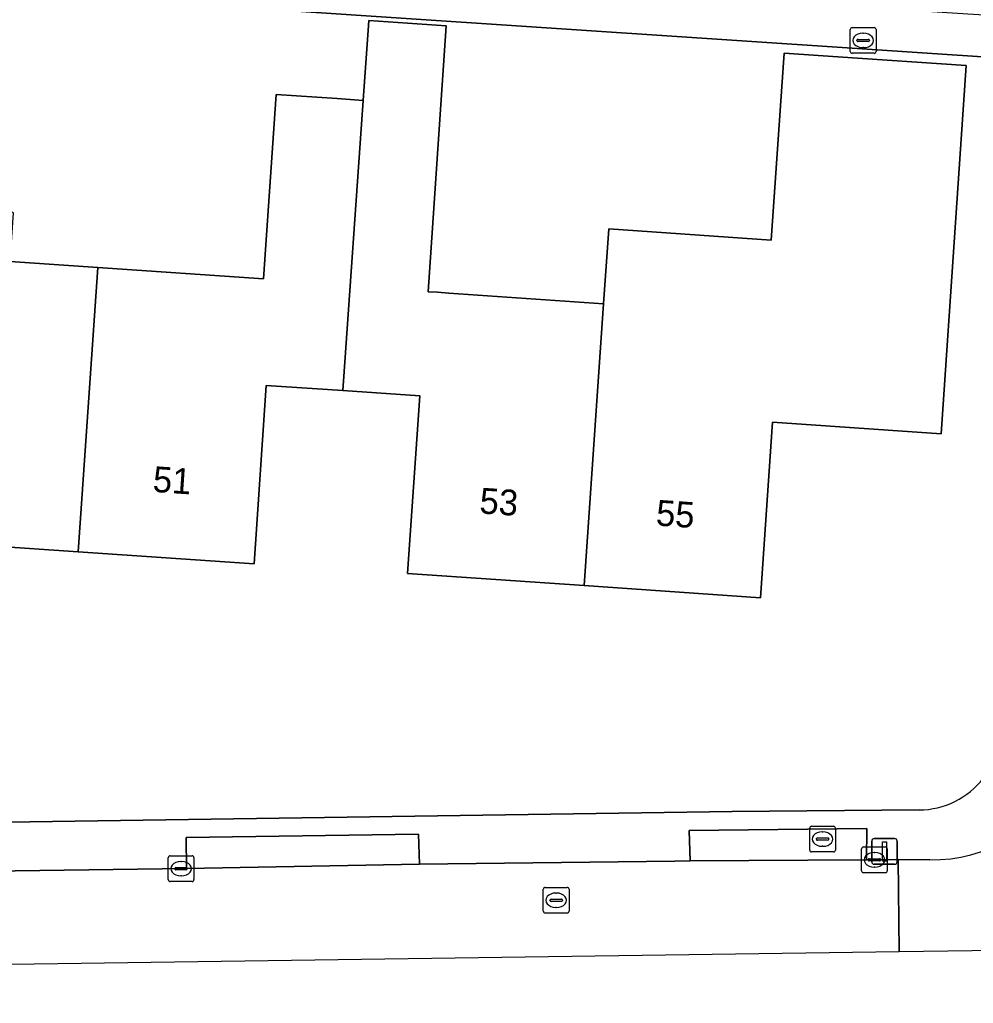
# Model space of a CAD drawing. Extents: x 161848 to 162726, y 385382 to 386521.
# Drawn here: x 162389.22 to 162426.27, y 385386.62 to 385424.82 of the extents above; entities that cross this region are included whole.
import ezdxf

# ---------------------------------------------------------------- set-up
doc = ezdxf.new("R2010")
doc.units = 0
for name, color, linetype in [('IMGEO_Brandkraan', 7, 'Continuous'), ('IMGEO_Erf', 7, 'Continuous'), ('IMGEO_Kolk', 7, 'Continuous'), ('IMGEO_Lichtmast', 7, 'Continuous'), ('IMGEO_Pand', 7, 'Continuous'), ('IMGEO_Pand_nummerreeks', 7, 'Continuous'), ('IMGEO_Rijbaan_lokaal_open', 7, 'Continuous'), ('IMGEO_Rioolput', 7, 'Continuous'), ('IMGEO_Voetpad_open', 7, 'Continuous')]:
    doc.layers.add(name, color=color, linetype=linetype)

msp = doc.modelspace()

# ---------------------------------------------------------------- linework, layer by layer
at = {"layer": 'IMGEO_Brandkraan'}
for p, q in [((162419.909, 385392.576), (162419.909, 385393.428)), ((162419.984, 385393.502), (162420.836, 385393.502)), ((162420.397, 385393.282), (162420.422, 385393.282)), ((162420.91, 385393.428), (162420.91, 385392.576)), ((162420.168, 385392.996), (162420.168, 385393.008)), ((162420.606, 385392.959), (162420.208, 385392.959)), ((162420.211, 385393.045), (162420.609, 385393.045)), ((162420.652, 385393.008), (162420.652, 385392.996)), ((162420.42, 385392.722), (162420.395, 385392.722)), ((162420.836, 385392.502), (162419.984, 385392.502))]:
    msp.add_line(p, q, dxfattribs=at)
for points in [[(162419.909, 385392.576), (162419.909, 385393.428)], [(162419.984, 385393.502), (162420.836, 385393.502)], [(162420.91, 385393.428), (162420.91, 385392.576)], [(162420.836, 385392.502), (162419.984, 385392.502)]]:
    msp.add_lwpolyline(points, dxfattribs=at)
for centre, radius, start, end in [((162419.986, 385393.426), 0.0765, 91.552, 178.448), ((162419.986, 385393.426), 0.0765, 91.552, 178.448), ((162420.834, 385393.426), 0.0765, 1.552, 88.448), ((162420.834, 385393.426), 0.0765, 1.552, 88.448), ((162420.208, 385393.005), 0.0403, 85.8775, 175.7526), ((162420.205, 385392.995), 0.0366, 178.938, 274.7102), ((162420.609, 385393.002), 0.043, 264.8664, 352.4533), ((162420.613, 385393.007), 0.0386, 1.7309, 96.639), ((162419.986, 385392.578), 0.0765, 181.552, 268.448), ((162419.986, 385392.578), 0.0765, 181.552, 268.448), ((162420.834, 385392.578), 0.0765, 271.552, 358.448), ((162420.834, 385392.578), 0.0765, 271.552, 358.448)]:
    msp.add_arc(centre, radius, start, end, dxfattribs=at)
for centre, major_axis, ratio, start_param, end_param in [((162420.396, 385393.002), (-0.387, 0.002), 0.722429, 4.712389, 7.853982), ((162420.421, 385393.002), (-0.39, 0.002), 0.717154, 1.570796, 4.712389)]:
    msp.add_ellipse(centre, major_axis=major_axis, ratio=ratio, start_param=start_param, end_param=end_param, dxfattribs=at)
at = {"layer": 'IMGEO_Erf'}
for points in [[(162427.854, 385404.175), (162428.958, 385423.219), (162280.836, 385433.091), (162278.626, 385400.728), (162278.251, 385395.589)], [(162388.854, 385415.432), (162392.263, 385415.198), (162398.691, 385414.756), (162399.183, 385421.92), (162401.557, 385421.757), (162402.564, 385421.688), (162402.767, 385424.601), (162402.78, 385424.787), (162405.795, 385424.58), (162405.782, 385424.394), (162405.087, 385414.26), (162405.447, 385414.235), (162405.896, 385414.204), (162411.904, 385413.792), (162412.106, 385416.704), (162418.419, 385416.266), (162418.712, 385420.541), (162418.916, 385423.516), (162420.999, 385423.377), (162425.987, 385423.044), (162425.015, 385408.738), (162418.466, 385409.188), (162417.998, 385402.376), (162411.145, 385402.847), (162404.288, 385403.319), (162404.762, 385410.211), (162401.78, 385410.416), (162398.801, 385410.621), (162398.325, 385403.69), (162391.498, 385404.159), (162384.67, 385404.628)], [(162281.355, 385392.086), (162416.901, 385394.073), (162424.16, 385394.133)]]:
    msp.add_lwpolyline(points, dxfattribs=at)
msp.add_arc((162424.135, 385397.328), 3.195, 270.4427, 322.2283, dxfattribs=at)
at = {"layer": 'IMGEO_Kolk'}
for p, q in [((162421.923, 385391.771), (162421.923, 385392.623)), ((162421.998, 385392.697), (162422.85, 385392.697)), ((162422.924, 385392.623), (162422.924, 385391.771)), ((162394.991, 385391.427), (162394.991, 385392.279)), ((162395.066, 385392.353), (162395.918, 385392.353)), ((162395.479, 385392.133), (162395.504, 385392.133)), ((162395.992, 385392.279), (162395.992, 385391.427)), ((162422.182, 385392.191), (162422.182, 385392.203)), ((162422.62, 385392.154), (162422.222, 385392.154)), ((162422.225, 385392.24), (162422.623, 385392.24)), ((162422.411, 385392.477), (162422.436, 385392.477)), ((162422.666, 385392.203), (162422.666, 385392.191)), ((162395.25, 385391.847), (162395.25, 385391.859)), ((162395.688, 385391.81), (162395.29, 385391.81)), ((162395.293, 385391.896), (162395.691, 385391.896)), ((162395.734, 385391.859), (162395.734, 385391.847)), ((162422.434, 385391.917), (162422.409, 385391.917)), ((162395.502, 385391.573), (162395.477, 385391.573)), ((162422.85, 385391.697), (162421.998, 385391.697)), ((162395.918, 385391.353), (162395.066, 385391.353))]:
    msp.add_line(p, q, dxfattribs=at)
for points in [[(162421.923, 385391.771), (162421.923, 385392.623)], [(162421.998, 385392.697), (162422.85, 385392.697)], [(162422.924, 385392.623), (162422.924, 385391.771)], [(162394.991, 385391.427), (162394.991, 385392.279)], [(162395.066, 385392.353), (162395.918, 385392.353)], [(162395.992, 385392.279), (162395.992, 385391.427)], [(162422.85, 385391.697), (162421.998, 385391.697)], [(162395.918, 385391.353), (162395.066, 385391.353)]]:
    msp.add_lwpolyline(points, dxfattribs=at)
for centre, radius, start, end in [((162422, 385392.621), 0.0765, 91.552, 178.448), ((162422, 385392.621), 0.0765, 91.552, 178.448), ((162422.848, 385392.621), 0.0765, 1.552, 88.448), ((162422.848, 385392.621), 0.0765, 1.552, 88.448), ((162395.068, 385392.277), 0.0765, 91.552, 178.448), ((162395.068, 385392.277), 0.0765, 91.552, 178.448), ((162395.916, 385392.277), 0.0765, 1.552, 88.448), ((162395.916, 385392.277), 0.0765, 1.552, 88.448), ((162422.222, 385392.2), 0.0403, 85.8775, 175.7526), ((162422.219, 385392.19), 0.0366, 178.938, 274.7102), ((162422.623, 385392.197), 0.043, 264.8664, 352.4533), ((162422.627, 385392.202), 0.0386, 1.7309, 96.639), ((162395.29, 385391.856), 0.0403, 85.8775, 175.7526), ((162395.287, 385391.846), 0.0366, 178.938, 274.7102), ((162395.691, 385391.853), 0.043, 264.8664, 352.4533), ((162395.695, 385391.858), 0.0386, 1.7309, 96.639), ((162422, 385391.773), 0.0765, 181.552, 268.448), ((162422, 385391.773), 0.0765, 181.552, 268.448), ((162422.848, 385391.773), 0.0765, 271.552, 358.448), ((162422.848, 385391.773), 0.0765, 271.552, 358.448), ((162395.068, 385391.429), 0.0765, 181.552, 268.448), ((162395.068, 385391.429), 0.0765, 181.552, 268.448), ((162395.916, 385391.429), 0.0765, 271.552, 358.448), ((162395.916, 385391.429), 0.0765, 271.552, 358.448)]:
    msp.add_arc(centre, radius, start, end, dxfattribs=at)
for centre, major_axis, ratio, start_param, end_param in [((162395.478, 385391.853), (-0.387, 0.002), 0.722429, 4.712389, 7.853982), ((162395.503, 385391.853), (-0.39, 0.002), 0.717154, 1.570796, 4.712389), ((162422.41, 385392.197), (-0.387, 0.002), 0.722429, 4.712389, 7.853982), ((162422.435, 385392.197), (-0.39, 0.002), 0.717154, 1.570796, 4.712389)]:
    msp.add_ellipse(centre, major_axis=major_axis, ratio=ratio, start_param=start_param, end_param=end_param, dxfattribs=at)
at = {"layer": 'IMGEO_Lichtmast'}
for p, q in [((162422.319, 385392.122), (162422.319, 385392.922)), ((162422.319, 385392.922), (162422.319, 385392.122)), ((162422.419, 385393.022), (162423.209, 385393.022)), ((162423.209, 385393.022), (162422.419, 385393.022)), ((162423.309, 385392.922), (162423.309, 385392.122)), ((162423.309, 385392.122), (162423.309, 385392.922)), ((162423.209, 385392.022), (162422.419, 385392.022)), ((162422.419, 385392.022), (162423.209, 385392.022))]:
    msp.add_line(p, q, dxfattribs=at)
msp.add_lwpolyline([(162422.739, 385392.897), (162422.889, 385392.897), (162422.889, 385392.147), (162422.739, 385392.147), (162422.739, 385392.897)], dxfattribs=at)
for centre, start, end in [((162422.419, 385392.922), 90, 180), ((162422.419, 385392.922), 90, 180), ((162423.209, 385392.922), 0, 90), ((162423.209, 385392.922), 360, 90), ((162422.419, 385392.122), 180, 270), ((162422.419, 385392.122), 180, 270), ((162423.209, 385392.122), 270, 0), ((162423.209, 385392.122), 270, 0)]:
    msp.add_arc(centre, 0.1, start, end, dxfattribs=at)
at = {"layer": 'IMGEO_Pand'}
for points in [[(162411.904, 385413.792), (162405.896, 385414.204), (162405.447, 385414.235), (162405.087, 385414.26), (162405.782, 385424.394), (162405.795, 385424.58), (162402.78, 385424.787), (162402.767, 385424.601), (162402.564, 385421.688), (162401.78, 385410.416), (162404.762, 385410.211), (162404.288, 385403.319), (162411.145, 385402.847)], [(162411.904, 385413.792), (162411.145, 385402.847), (162417.998, 385402.376), (162418.466, 385409.188), (162425.015, 385408.738), (162425.987, 385423.044), (162420.999, 385423.377), (162418.916, 385423.516), (162418.712, 385420.541), (162418.419, 385416.266), (162412.106, 385416.704)], [(162392.263, 385415.198), (162388.854, 385415.432), (162388.984, 385417.317), (162387.412, 385418.17), (162385.927, 385418.272), (162386.22, 385422.536), (162386.237, 385422.778), (162382.95, 385423.004), (162382.168, 385411.729), (162385.143, 385411.524), (162384.67, 385404.628), (162391.498, 385404.159)], [(162402.564, 385421.688), (162401.557, 385421.757), (162399.183, 385421.92), (162398.691, 385414.756), (162392.263, 385415.198), (162391.498, 385404.159), (162398.325, 385403.69), (162398.801, 385410.621), (162401.78, 385410.416)]]:
    msp.add_lwpolyline(points, close=True, dxfattribs=at)
at = {"layer": 'IMGEO_Rijbaan_lokaal_open'}
msp.add_lwpolyline([(162283.627, 385386.624), (162311.689, 385387.041), (162423.379, 385388.63), (162423.345, 385392.207), (162422.114, 385392.193), (162415.263, 385392.152), (162414.667, 385392.145), (162404.752, 385392.031), (162395.708, 385391.856), (162385.244, 385391.714), (162376.255, 385391.567), (162365.438, 385391.402), (162356.466, 385391.274), (162345.675, 385391.109), (162336.847, 385390.975), (162326.07, 385390.811), (162317.048, 385390.66), (162305.98, 385390.533), (162297.003, 385390.375), (162288.6, 385390.263), (162283.574, 385390.167), (162283.627, 385386.624)], close=True, dxfattribs=at)
msp.add_lwpolyline([(162424.58, 385392.199), (162423.345, 385392.207), (162423.379, 385388.63), (162443.225, 385388.912)], dxfattribs=at)
msp.add_arc((162424.714, 385397.67), 5.472, 268.5993, 335.1607, dxfattribs=at)
at = {"layer": 'IMGEO_Rioolput'}
for p, q in [((162421.487, 385423.59), (162421.487, 385424.442)), ((162421.562, 385424.516), (162422.414, 385424.516)), ((162421.975, 385424.296), (162422, 385424.296)), ((162422.488, 385424.442), (162422.488, 385423.59)), ((162421.746, 385424.01), (162421.746, 385424.022)), ((162422.184, 385423.973), (162421.786, 385423.973)), ((162421.789, 385424.059), (162422.187, 385424.059)), ((162422.23, 385424.022), (162422.23, 385424.01)), ((162422.414, 385423.516), (162421.562, 385423.516)), ((162421.998, 385423.736), (162421.973, 385423.736)), ((162409.563, 385390.2), (162409.563, 385391.052)), ((162409.638, 385391.126), (162410.49, 385391.126)), ((162410.564, 385391.052), (162410.564, 385390.2)), ((162409.822, 385390.62), (162409.822, 385390.632)), ((162409.865, 385390.669), (162410.263, 385390.669)), ((162410.051, 385390.906), (162410.076, 385390.906)), ((162410.306, 385390.632), (162410.306, 385390.62)), ((162410.26, 385390.583), (162409.862, 385390.583)), ((162410.074, 385390.346), (162410.049, 385390.346)), ((162410.49, 385390.126), (162409.638, 385390.126))]:
    msp.add_line(p, q, dxfattribs=at)
for points in [[(162421.487, 385423.59), (162421.487, 385424.442)], [(162421.562, 385424.516), (162422.414, 385424.516)], [(162422.488, 385424.442), (162422.488, 385423.59)], [(162422.414, 385423.516), (162421.562, 385423.516)], [(162409.563, 385390.2), (162409.563, 385391.052)], [(162409.638, 385391.126), (162410.49, 385391.126)], [(162410.564, 385391.052), (162410.564, 385390.2)], [(162410.49, 385390.126), (162409.638, 385390.126)]]:
    msp.add_lwpolyline(points, dxfattribs=at)
for centre, radius, start, end in [((162421.564, 385424.44), 0.0765, 91.552, 178.448), ((162421.564, 385424.44), 0.0765, 91.552, 178.448), ((162422.412, 385424.44), 0.0765, 1.552, 88.448), ((162422.412, 385424.44), 0.0765, 1.552, 88.448), ((162421.786, 385424.019), 0.0403, 85.8775, 175.7526), ((162421.783, 385424.009), 0.0366, 178.938, 274.7102), ((162422.187, 385424.016), 0.043, 264.8664, 352.4533), ((162422.191, 385424.021), 0.0386, 1.7309, 96.639), ((162421.564, 385423.592), 0.0765, 181.552, 268.448), ((162421.564, 385423.592), 0.0765, 181.552, 268.448), ((162422.412, 385423.592), 0.0765, 271.552, 358.448), ((162422.412, 385423.592), 0.0765, 271.552, 358.448), ((162409.64, 385391.05), 0.0765, 91.552, 178.448), ((162409.64, 385391.05), 0.0765, 91.552, 178.448), ((162410.488, 385391.05), 0.0765, 1.552, 88.448), ((162410.488, 385391.05), 0.0765, 1.552, 88.448), ((162409.862, 385390.629), 0.0403, 85.8775, 175.7526), ((162409.859, 385390.619), 0.0366, 178.938, 274.7102), ((162410.263, 385390.626), 0.043, 264.8664, 352.4533), ((162410.267, 385390.631), 0.0386, 1.7309, 96.639), ((162409.64, 385390.202), 0.0765, 181.552, 268.448), ((162409.64, 385390.202), 0.0765, 181.552, 268.448), ((162410.488, 385390.202), 0.0765, 271.552, 358.448), ((162410.488, 385390.202), 0.0765, 271.552, 358.448)]:
    msp.add_arc(centre, radius, start, end, dxfattribs=at)
for centre, major_axis, ratio, start_param, end_param in [((162421.974, 385424.016), (-0.387, 0.002), 0.722429, 4.712389, 7.853982), ((162421.999, 385424.016), (-0.39, 0.002), 0.717154, 1.570796, 4.712389), ((162410.05, 385390.626), (-0.387, 0.002), 0.722429, 4.712389, 7.853982), ((162410.075, 385390.626), (-0.39, 0.002), 0.717154, 1.570796, 4.712389)]:
    msp.add_ellipse(centre, major_axis=major_axis, ratio=ratio, start_param=start_param, end_param=end_param, dxfattribs=at)
at = {"layer": 'IMGEO_Voetpad_open'}
for points in [[(162280.836, 385433.091), (162428.958, 385423.219), (162429.053, 385424.859), (162426.05, 385425.033), (162416.476, 385425.669), (162415.971, 385425.703), (162414.028, 385425.832), (162409.861, 385425.954), (162404.208, 385426.258), (162401.284, 385426.416), (162398.524, 385426.565), (162395.223, 385426.793), (162395.237, 385427.18), (162392.289, 385427.289), (162390.12, 385427.37), (162383.076, 385427.896)], [(162424.16, 385394.133), (162416.901, 385394.073), (162281.355, 385392.086)], [(162336.813, 385392.155), (162345.646, 385392.311), (162345.675, 385391.109), (162356.466, 385391.274), (162356.429, 385392.461), (162365.413, 385392.603), (162365.438, 385391.402), (162376.255, 385391.567), (162376.238, 385392.768), (162385.208, 385392.902), (162385.244, 385391.714), (162395.708, 385391.856), (162395.691, 385393.067), (162404.714, 385393.196), (162404.752, 385392.031), (162414.667, 385392.145), (162415.263, 385392.152), (162415.231, 385393.339), (162422.125, 385393.414), (162422.114, 385392.193), (162423.345, 385392.207), (162424.58, 385392.199)]]:
    msp.add_lwpolyline(points, dxfattribs=at)
for points in [[(162415.263, 385392.152), (162422.114, 385392.193), (162422.125, 385393.414), (162415.231, 385393.339)], [(162404.752, 385392.031), (162404.714, 385393.196), (162395.691, 385393.067), (162395.708, 385391.856)]]:
    msp.add_lwpolyline(points, close=True, dxfattribs=at)
for centre, radius, start, end in [((162424.135, 385397.328), 3.195, 270.4427, 322.2283), ((162424.714, 385397.67), 5.472, 268.5993, 335.1607)]:
    msp.add_arc(centre, radius, start, end, dxfattribs=at)

# ---------------------------------------------------------------- texts
at = {"layer": 'IMGEO_Pand_nummerreeks'}
for s, rotation, p in [('51', 356.0695, (162394.372, 385406.487)), ('53', 356.0638, (162407.063, 385405.653)), ('55', 356.0638, (162413.918, 385405.182))]:
    msp.add_text(s, height=1, rotation=rotation, dxfattribs=at).set_placement(p)

doc.saveas('drawing.dxf')
